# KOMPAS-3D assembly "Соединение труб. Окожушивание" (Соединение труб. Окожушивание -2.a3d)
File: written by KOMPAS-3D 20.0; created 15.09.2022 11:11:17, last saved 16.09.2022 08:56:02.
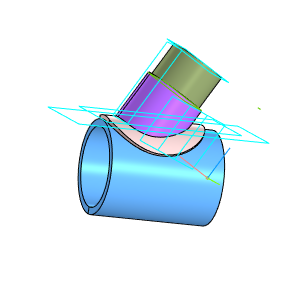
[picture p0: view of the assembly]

Document properties: Полное имя файла: D:\YAKOVLEV\ПРОЕКТЫ\ДЦ-2. ДП-7 Газопровод Окожушивание\ПРОБА Соединение труб. Окожушивание\ПРОБА 2\Соединение труб. Окожушивание -2.a3d

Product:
- Part/product: Соединение труб. Окожушивание
    Масса: 24816
  - Component [assembly]: Соединение труб  | Масса: 21154.1; source file: Соединение труб.a3d
  - Component [detail]: Кожух 1  | Материал: Сталь 45  ГОСТ 1050-2013 (density 7810 kg/m3); Масса: 1603.28; source file: Кожух 1.m3d
  - Component [detail]: Кожух 2  | Материал: Сталь 45  ГОСТ 1050-2013 (density 7810 kg/m3); Масса: 2058.57; source file: Кожух 2.m3d

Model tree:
1. Смещенная плоскость:1  (with: Обечайка:1)
     Расстояние = 800

Referenced files in D:\YAKOVLEV\ПРОЕКТЫ\ДЦ-2. ДП-7 Газопровод Окожушивание\ПРОБА Соединение труб. Окожушивание\ПРОБА 2\: Соединение труб.a3d, Кожух 1.m3d, Кожух 2.m3d
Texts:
  Точка начала. Х
  Точка начала. Y
  Точка начала. Z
